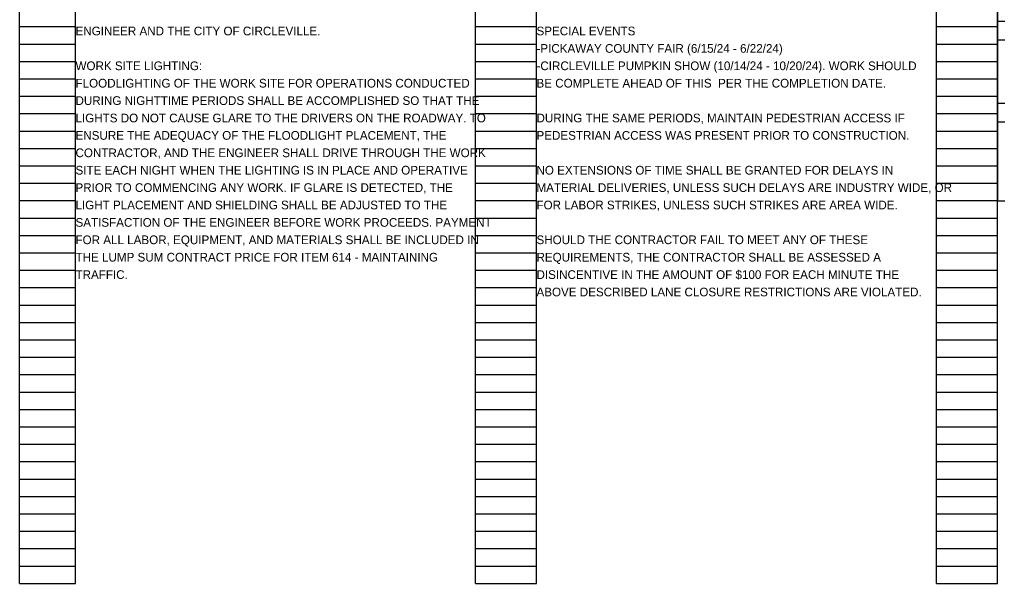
# Model space of a CAD drawing. Extents: x 24172 to 24226.9, y 11011.9 to 11091.2.
# Drawn here: x 24196.45 to 24212.19, y 11071.02 to 11080.09 of the extents above; entities that cross this region are included whole.
import ezdxf

# ---------------------------------------------------------------- set-up
doc = ezdxf.new("R2010")
doc.units = 0
for name, color, linetype in [('SC_Scratch1', 7, 'Continuous'), ('SH_Data', 7, 'Continuous'), ('SH_Text', 7, 'Continuous')]:
    doc.layers.add(name, color=color, linetype=linetype)

msp = doc.modelspace()

# ---------------------------------------------------------------- linework, layer by layer
at = {"layer": 'SH_Data'}
for p, q in [((24196.45, 11071.019), (24196.45, 11091.179)), ((24197.35, 11071.019), (24197.35, 11091.179)), ((24203.79, 11071.019), (24203.79, 11091.179)), ((24204.77, 11071.019), (24204.77, 11091.179)), ((24211.21, 11071.019), (24211.21, 11091.179)), ((24212.19, 11071.019), (24212.19, 11091.179)), ((24196.45, 11079.979), (24197.35, 11079.979)), ((24203.79, 11079.979), (24204.77, 11079.979)), ((24211.21, 11079.979), (24212.19, 11079.979)), ((24196.45, 11079.699), (24197.35, 11079.699)), ((24203.79, 11079.699), (24204.77, 11079.699)), ((24211.21, 11079.699), (24212.19, 11079.699)), ((24196.45, 11079.419), (24197.35, 11079.419)), ((24203.79, 11079.419), (24204.77, 11079.419)), ((24211.21, 11079.419), (24212.19, 11079.419)), ((24196.45, 11079.139), (24197.35, 11079.139)), ((24203.79, 11079.139), (24204.77, 11079.139)), ((24211.21, 11079.139), (24212.19, 11079.139)), ((24196.45, 11078.859), (24197.35, 11078.859)), ((24203.79, 11078.859), (24204.77, 11078.859)), ((24211.21, 11078.859), (24212.19, 11078.859)), ((24196.45, 11078.579), (24197.35, 11078.579)), ((24203.79, 11078.579), (24204.77, 11078.579)), ((24211.21, 11078.579), (24212.19, 11078.579)), ((24196.45, 11078.299), (24197.35, 11078.299)), ((24203.79, 11078.299), (24204.77, 11078.299)), ((24211.21, 11078.299), (24212.19, 11078.299)), ((24196.45, 11078.019), (24197.35, 11078.019)), ((24203.79, 11078.019), (24204.77, 11078.019)), ((24211.21, 11078.019), (24212.19, 11078.019)), ((24196.45, 11077.739), (24197.35, 11077.739)), ((24203.79, 11077.739), (24204.77, 11077.739)), ((24211.21, 11077.739), (24212.19, 11077.739)), ((24196.45, 11077.459), (24197.35, 11077.459)), ((24203.79, 11077.459), (24204.77, 11077.459)), ((24211.21, 11077.459), (24212.19, 11077.459)), ((24196.45, 11077.179), (24197.35, 11077.179)), ((24203.79, 11077.179), (24204.77, 11077.179)), ((24211.21, 11077.179), (24212.19, 11077.179)), ((24196.45, 11076.899), (24197.35, 11076.899)), ((24203.79, 11076.899), (24204.77, 11076.899)), ((24211.21, 11076.899), (24212.19, 11076.899)), ((24196.45, 11076.619), (24197.35, 11076.619)), ((24203.79, 11076.619), (24204.77, 11076.619)), ((24211.21, 11076.619), (24212.19, 11076.619)), ((24196.45, 11076.339), (24197.35, 11076.339)), ((24203.79, 11076.339), (24204.77, 11076.339)), ((24211.21, 11076.339), (24212.19, 11076.339)), ((24196.45, 11076.059), (24197.35, 11076.059)), ((24203.79, 11076.059), (24204.77, 11076.059)), ((24211.21, 11076.059), (24212.19, 11076.059)), ((24196.45, 11075.779), (24197.35, 11075.779)), ((24203.79, 11075.779), (24204.77, 11075.779)), ((24211.21, 11075.779), (24212.19, 11075.779)), ((24196.45, 11075.499), (24197.35, 11075.499)), ((24203.79, 11075.499), (24204.77, 11075.499)), ((24211.21, 11075.499), (24212.19, 11075.499)), ((24196.45, 11075.219), (24197.35, 11075.219)), ((24203.79, 11075.219), (24204.77, 11075.219)), ((24211.21, 11075.219), (24212.19, 11075.219)), ((24196.45, 11074.939), (24197.35, 11074.939)), ((24203.79, 11074.939), (24204.77, 11074.939)), ((24211.21, 11074.939), (24212.19, 11074.939)), ((24196.45, 11074.659), (24197.35, 11074.659)), ((24203.79, 11074.659), (24204.77, 11074.659)), ((24211.21, 11074.659), (24212.19, 11074.659)), ((24196.45, 11074.379), (24197.35, 11074.379)), ((24203.79, 11074.379), (24204.77, 11074.379)), ((24211.21, 11074.379), (24212.19, 11074.379)), ((24196.45, 11074.099), (24197.35, 11074.099)), ((24203.79, 11074.099), (24204.77, 11074.099)), ((24211.21, 11074.099), (24212.19, 11074.099)), ((24196.45, 11073.819), (24197.35, 11073.819)), ((24203.79, 11073.819), (24204.77, 11073.819)), ((24211.21, 11073.819), (24212.19, 11073.819)), ((24196.45, 11073.539), (24197.35, 11073.539)), ((24203.79, 11073.539), (24204.77, 11073.539)), ((24211.21, 11073.539), (24212.19, 11073.539)), ((24196.45, 11073.259), (24197.35, 11073.259)), ((24203.79, 11073.259), (24204.77, 11073.259)), ((24211.21, 11073.259), (24212.19, 11073.259)), ((24196.45, 11072.979), (24197.35, 11072.979)), ((24203.79, 11072.979), (24204.77, 11072.979)), ((24211.21, 11072.979), (24212.19, 11072.979)), ((24196.45, 11072.699), (24197.35, 11072.699)), ((24203.79, 11072.699), (24204.77, 11072.699)), ((24211.21, 11072.699), (24212.19, 11072.699)), ((24196.45, 11072.419), (24197.35, 11072.419)), ((24203.79, 11072.419), (24204.77, 11072.419)), ((24211.21, 11072.419), (24212.19, 11072.419)), ((24196.45, 11072.139), (24197.35, 11072.139)), ((24203.79, 11072.139), (24204.77, 11072.139)), ((24211.21, 11072.139), (24212.19, 11072.139)), ((24196.45, 11071.859), (24197.35, 11071.859)), ((24203.79, 11071.859), (24204.77, 11071.859)), ((24211.21, 11071.859), (24212.19, 11071.859)), ((24196.45, 11071.579), (24197.35, 11071.579)), ((24203.79, 11071.579), (24204.77, 11071.579)), ((24211.21, 11071.579), (24212.19, 11071.579)), ((24196.45, 11071.299), (24197.35, 11071.299)), ((24203.79, 11071.299), (24204.77, 11071.299)), ((24211.21, 11071.299), (24212.19, 11071.299)), ((24196.45, 11071.019), (24197.35, 11071.019)), ((24203.79, 11071.019), (24204.77, 11071.019)), ((24211.21, 11071.019), (24212.19, 11071.019))]:
    msp.add_line(p, q, dxfattribs=at)
at = {"layer": 'SH_Text'}
for p, q in [((24212.19, 11082.499), (24212.19, 11077.174)), ((24212.19, 11080.069), (24218.58, 11080.069)), ((24212.19, 11079.769), (24218.58, 11079.769)), ((24212.19, 11078.749), (24218.58, 11078.749)), ((24212.19, 11078.449), (24218.58, 11078.449)), ((24212.19, 11077.174), (24218.58, 11077.174))]:
    msp.add_line(p, q, dxfattribs=at)

# ---------------------------------------------------------------- texts
at = {"layer": 'SC_Scratch1'}
for s, p in [('ENGINEER AND THE CITY OF CIRCLEVILLE.', (24197.35, 11079.839)), ('WORK SITE LIGHTING:', (24197.35, 11079.279)), ('FLOODLIGHTING OF THE WORK SITE FOR OPERATIONS CONDUCTED ', (24197.35, 11078.999)), ('DURING NIGHTTIME PERIODS SHALL BE ACCOMPLISHED SO THAT THE ', (24197.35, 11078.719)), ('LIGHTS DO NOT CAUSE GLARE TO THE DRIVERS ON THE ROADWAY. TO ', (24197.35, 11078.439)), ('ENSURE THE ADEQUACY OF THE FLOODLIGHT PLACEMENT, THE ', (24197.35, 11078.159)), ('CONTRACTOR, AND THE ENGINEER SHALL DRIVE THROUGH THE WORK ', (24197.35, 11077.879)), ('SITE EACH NIGHT WHEN THE LIGHTING IS IN PLACE AND OPERATIVE ', (24197.35, 11077.599)), ('PRIOR TO COMMENCING ANY WORK. IF GLARE IS DETECTED, THE ', (24197.35, 11077.319)), ('LIGHT PLACEMENT AND SHIELDING SHALL BE ADJUSTED TO THE ', (24197.35, 11077.039)), ('SATISFACTION OF THE ENGINEER BEFORE WORK PROCEEDS. PAYMENT ', (24197.35, 11076.759)), ('FOR ALL LABOR, EQUIPMENT, AND MATERIALS SHALL BE INCLUDED IN ', (24197.35, 11076.479)), ('THE LUMP SUM CONTRACT PRICE FOR ITEM 614 - MAINTAINING ', (24197.35, 11076.199)), ('TRAFFIC.', (24197.35, 11075.919))]:
    msp.add_text(s, height=0.14, dxfattribs=at).set_placement(p)
at = {"layer": 'SH_Data'}
for s, p in [('SPECIAL EVENTS', (24204.77, 11079.839)), ('-PICKAWAY COUNTY FAIR (6/15/24 - 6/22/24)', (24204.77, 11079.559)), ('-CIRCLEVILLE PUMPKIN SHOW (10/14/24 - 10/20/24). WORK SHOULD ', (24204.77, 11079.279)), ('BE COMPLETE AHEAD OF THIS  PER THE COMPLETION DATE. ', (24204.77, 11078.999)), ('DURING THE SAME PERIODS, MAINTAIN PEDESTRIAN ACCESS IF ', (24204.77, 11078.439)), ('PEDESTRIAN ACCESS WAS PRESENT PRIOR TO CONSTRUCTION. ', (24204.77, 11078.159)), ('NO EXTENSIONS OF TIME SHALL BE GRANTED FOR DELAYS IN ', (24204.77, 11077.599)), ('MATERIAL DELIVERIES, UNLESS SUCH DELAYS ARE INDUSTRY WIDE, OR ', (24204.77, 11077.319)), ('FOR LABOR STRIKES, UNLESS SUCH STRIKES ARE AREA WIDE.', (24204.77, 11077.039)), ('SHOULD THE CONTRACTOR FAIL TO MEET ANY OF THESE ', (24204.77, 11076.479)), ('REQUIREMENTS, THE CONTRACTOR SHALL BE ASSESSED A ', (24204.77, 11076.199)), ('DISINCENTIVE IN THE AMOUNT OF $100 FOR EACH MINUTE THE ', (24204.77, 11075.919)), ('ABOVE DESCRIBED LANE CLOSURE RESTRICTIONS ARE VIOLATED.', (24204.77, 11075.639))]:
    msp.add_text(s, height=0.14, dxfattribs=at).set_placement(p)

doc.saveas('drawing.dxf')
